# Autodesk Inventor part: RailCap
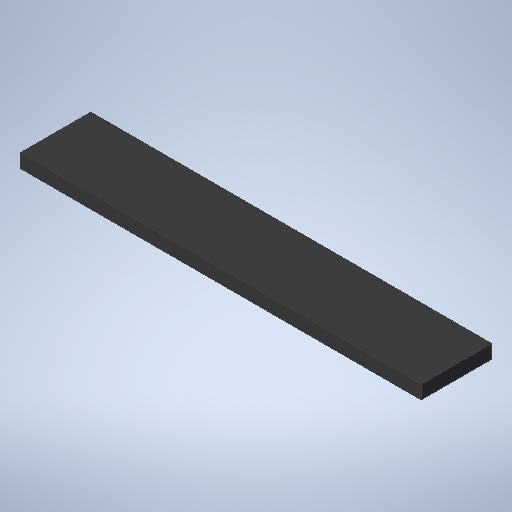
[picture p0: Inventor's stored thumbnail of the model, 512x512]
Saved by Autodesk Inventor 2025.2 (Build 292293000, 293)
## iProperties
Created: 2025-10
Part Number: RailCap
Material: Generic
Document SubType Name: Modeling
Designer: tyler
Density: 1 g/cm^3
Appearance: Default
Author: tyler
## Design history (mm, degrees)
sketch "Sketch1"
  geometry: L1 (23.495, -4.128)-(-23.495, -4.128); L2 (-23.495, -4.128)-(-23.495, 4.128); L3 (-23.495, 4.128)-(23.495, 4.128); L4 (23.495, 4.128)-(23.495, -4.128); L5 (23.495, -4.128)-(-23.495, 4.128); L6 (-23.495, -4.128)-(23.495, 4.128); 1 further point
  constraints: 12 end point, 2 midpoint, 2 parallel, 1 horizontal, 1 perpendicular
  dimensions: "d0" = 46.99 distance of L2.end L3.end; "d1" = 8.255 distance of L1.end L2.end
extrude "Extrusion1" new body sketch "Sketch1" distance "d2" = 1.5875; taper "d3" = 0 deg
body "Solid1"
